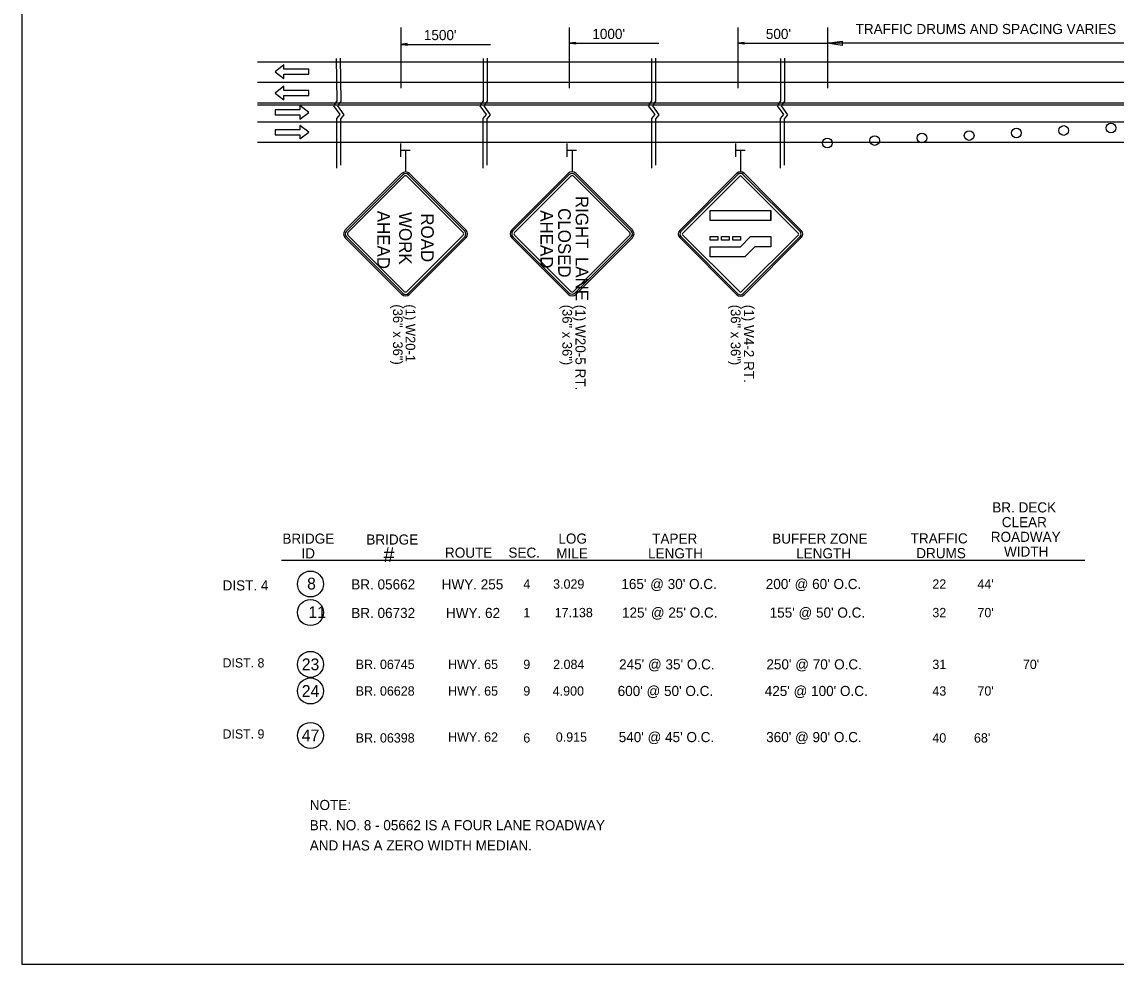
# Model space of a CAD drawing. Extents: x 1930579 to 1938013, y 596452 to 597673.
# Drawn here: x 1936313 to 1936962, y 596573 to 597133 of the extents above; entities that cross this region are included whole.
import ezdxf

# ---------------------------------------------------------------- set-up
doc = ezdxf.new("R2010")
doc.units = 0
for name, color, linetype in [('Default', 7, 'Continuous'), ('P_TC_Signs_Permanent', 7, 'Continuous'), ('P_TC_Signs_Temporary', 7, 'Continuous'), ('R_Border', 7, 'Continuous'), ('R_Striping', 7, 'Continuous'), ('S_AREA_CALC', 7, 'Continuous')]:
    doc.layers.add(name, color=color, linetype=linetype)

msp = doc.modelspace()

# ---------------------------------------------------------------- linework, layer by layer
at = {"layer": 'Default'}
for p, q in [((1936537.79, 597129.19), (1936537.79, 597093.28)), ((1936637.79, 597129.19), (1936637.79, 597093.28)), ((1936737.79, 597129.19), (1936737.79, 597093.28)), ((1936791.02, 597129.19), (1936791.02, 597093.28)), ((1936541.62, 597119.78), (1936537.79, 597119.21)), ((1936537.79, 597119.21), (1936591.02, 597119.21)), ((1936541.62, 597118.63), (1936537.79, 597119.21)), ((1936541.62, 597119.68), (1936538.43, 597119.21)), ((1936541.62, 597118.73), (1936538.43, 597119.21)), ((1936541.62, 597119.59), (1936539.09, 597119.21)), ((1936541.62, 597118.83), (1936539.09, 597119.21)), ((1936541.62, 597119.49), (1936539.73, 597119.21)), ((1936541.62, 597118.92), (1936539.73, 597119.21)), ((1936541.62, 597119.39), (1936540.37, 597119.21)), ((1936541.62, 597119.02), (1936540.37, 597119.21)), ((1936541.62, 597119.3), (1936541.01, 597119.21)), ((1936541.62, 597119.12), (1936541.01, 597119.21)), ((1936541.62, 597118.63), (1936541.62, 597119.78)), ((1936641.62, 597120.46), (1936637.79, 597119.89)), ((1936637.79, 597119.89), (1936691.02, 597119.89)), ((1936641.62, 597119.31), (1936637.79, 597119.89)), ((1936641.62, 597120.36), (1936638.43, 597119.89)), ((1936641.62, 597119.41), (1936638.43, 597119.89)), ((1936641.62, 597120.27), (1936639.09, 597119.89)), ((1936641.62, 597119.51), (1936639.09, 597119.89)), ((1936641.62, 597120.17), (1936639.73, 597119.89)), ((1936641.62, 597119.6), (1936639.73, 597119.89)), ((1936641.62, 597120.07), (1936640.37, 597119.89)), ((1936641.62, 597119.7), (1936640.37, 597119.89)), ((1936641.62, 597119.98), (1936641.01, 597119.89)), ((1936641.62, 597119.8), (1936641.01, 597119.89)), ((1936641.62, 597119.31), (1936641.62, 597120.46)), ((1936741.62, 597120.46), (1936737.79, 597119.89)), ((1936737.79, 597119.89), (1936791.02, 597119.89)), ((1936741.62, 597119.31), (1936737.79, 597119.89)), ((1936741.62, 597120.36), (1936738.43, 597119.89)), ((1936741.62, 597119.41), (1936738.43, 597119.89)), ((1936741.62, 597120.27), (1936739.09, 597119.89)), ((1936741.62, 597119.51), (1936739.09, 597119.89)), ((1936741.62, 597120.17), (1936739.73, 597119.89)), ((1936741.62, 597119.6), (1936739.73, 597119.89)), ((1936741.62, 597120.07), (1936740.37, 597119.89)), ((1936741.62, 597119.7), (1936740.37, 597119.89)), ((1936741.62, 597119.98), (1936741.01, 597119.89)), ((1936741.62, 597119.8), (1936741.01, 597119.89)), ((1936741.62, 597119.31), (1936741.62, 597120.46)), ((1936791.02, 597119.89), (1936799.89, 597121.22)), ((1937015.53, 597119.89), (1936791.02, 597119.89)), ((1936799.89, 597118.56), (1936791.02, 597119.89)), ((1936799.89, 597121.22), (1936799.89, 597118.56)), ((1937804.86, 597108.65), (1936452.69, 597108.65)), ((1937804.86, 597096.65), (1936452.69, 597096.65)), ((1937804.86, 597084.42), (1936452.69, 597084.42)), ((1937804.86, 597083.27), (1936452.69, 597083.27)), ((1937804.86, 597073.09), (1936452.69, 597073.09)), ((1937804.86, 597061.09), (1936452.69, 597061.09)), ((1936537.79, 597052.49), (1936537.79, 597060.47)), ((1936636.62, 597052.43), (1936636.62, 597060.41)), ((1936736.62, 597052.43), (1936736.62, 597060.41)), ((1936537.91, 597056.46), (1936543.36, 597056.46)), ((1936636.74, 597056.4), (1936642.18, 597056.4)), ((1936736.74, 597056.4), (1936742.18, 597056.4))]:
    msp.add_line(p, q, dxfattribs=at)
for points in [[(1936499.33, 597110.93), (1936499.72, 597085.69), (1936497.77, 597082.8), (1936501.57, 597077.6), (1936499.57, 597075.2), (1936499.56, 597045.85)], [(1936501.73, 597111.16), (1936502.12, 597085.59), (1936500.17, 597082.7), (1936503.96, 597077.5), (1936501.96, 597075.1), (1936501.96, 597047.54)], [(1936586.69, 597110.93), (1936586.69, 597085.69), (1936584.74, 597082.8), (1936588.54, 597077.6), (1936586.54, 597075.2), (1936586.54, 597045.85)], [(1936589.09, 597111.16), (1936589.09, 597085.59), (1936587.14, 597082.7), (1936590.94, 597077.5), (1936588.94, 597075.1), (1936588.94, 597047.54)], [(1936686.69, 597110.93), (1936686.69, 597085.69), (1936684.74, 597082.8), (1936688.54, 597077.6), (1936686.54, 597075.2), (1936686.54, 597045.85)], [(1936689.09, 597111.16), (1936689.09, 597085.59), (1936687.14, 597082.7), (1936690.94, 597077.5), (1936688.94, 597075.1), (1936688.94, 597047.54)], [(1936763.16, 597110.93), (1936763.16, 597085.69), (1936761.21, 597082.8), (1936765.01, 597077.6), (1936763.01, 597075.2), (1936763, 597045.85)], [(1936765.56, 597111.16), (1936765.56, 597085.59), (1936763.61, 597082.7), (1936767.4, 597077.5), (1936765.41, 597075.1), (1936765.4, 597047.54)]]:
    msp.add_lwpolyline(points, dxfattribs=at)
for centre, radius in [((1936931.34, 597068.14), 2.87), ((1936959.4, 597069.63), 2.87), ((1936819.09, 597062.2), 2.87), ((1936847.15, 597063.68), 2.87), ((1936875.21, 597065.17), 2.87), ((1936903.28, 597066.66), 2.87), ((1936791.02, 597060.71), 2.87), ((1936484.14, 596798.97), 7.71), ((1936484.14, 596782.01), 7.71), ((1936484.14, 596751.28), 7.71), ((1936484.14, 596735.48), 7.71), ((1936484.14, 596709.1), 7.71)]:
    msp.add_circle(centre, radius, dxfattribs=at)
at = {"layer": 'P_TC_Signs_Permanent'}
for p, q in [((1936703.4, 597008.78), (1936737.34, 597042.72)), ((1936757.46, 597014.7), (1936757.46, 597020.7)), ((1936737.34, 596970.6), (1936703.4, 597004.54)), ((1936775.52, 597004.54), (1936741.58, 596970.6))]:
    msp.add_line(p, q, dxfattribs=at)
for points in [[(1936737.97, 597042.08), (1936704.03, 597008.14)], [(1936705.09, 597007.08), (1936739.04, 597041.02)], [(1936739.88, 597041.02), (1936773.82, 597007.08)], [(1936774.89, 597008.14), (1936740.94, 597042.08)], [(1936741.58, 597042.72), (1936758.55, 597025.75), (1936775.52, 597008.78)], [(1936739.04, 596972.29), (1936705.09, 597006.23)], [(1936773.82, 597006.23), (1936739.88, 596972.29)], [(1936704.03, 597005.17), (1936737.97, 596971.23)], [(1936740.94, 596971.23), (1936774.89, 597005.17)]]:
    msp.add_lwpolyline(points, dxfattribs=at)
for points in [[(1936721.46, 597014.7), (1936721.46, 597020.7), (1936757.46, 597020.7), (1936757.46, 597014.7)], [(1936721.46, 597003.06), (1936721.46, 597005.16), (1936725.96, 597005.16), (1936725.96, 597003.06)], [(1936721.46, 596993.16), (1936721.46, 596999.16), (1936739.46, 596999.16), (1936745.46, 597005.16), (1936757.46, 597005.16), (1936757.46, 596999.16), (1936747.94, 596999.16), (1936741.94, 596993.16)], [(1936728.21, 597003.06), (1936728.21, 597005.16), (1936732.71, 597005.16), (1936732.71, 597003.06)], [(1936734.96, 597003.06), (1936734.96, 597005.16), (1936739.46, 597005.16), (1936739.46, 597003.06)]]:
    msp.add_lwpolyline(points, close=True, dxfattribs=at)
for centre, radius, start, end in [((1936739.46, 597040.6), 3, 45, 135), ((1936739.46, 597040.6), 2.1, 45, 135), ((1936739.46, 597040.6), 0.6, 45, 135), ((1936705.52, 597006.66), 3, 135, 225), ((1936705.52, 597006.66), 2.1, 135, 225), ((1936705.52, 597006.66), 0.6, 135, 225), ((1936773.4, 597006.66), 0.6, 315, 45), ((1936773.4, 597006.66), 2.1, 315, 45), ((1936773.4, 597006.66), 3, 315, 45), ((1936739.46, 596972.72), 3, 225, 315), ((1936739.46, 596972.72), 2.1, 225, 315), ((1936739.46, 596972.72), 0.6, 225, 315)]:
    msp.add_arc(centre, radius, start, end, dxfattribs=at)
at = {"layer": 'P_TC_Signs_Temporary'}
for p, q in [((1936504.84, 597009.13), (1936538.25, 597042.54)), ((1936505.5, 597008.46), (1936538.91, 597041.88)), ((1936506.43, 597007.54), (1936539.84, 597040.95)), ((1936541.43, 597040.95), (1936574.84, 597007.54)), ((1936542.36, 597041.88), (1936575.77, 597008.46)), ((1936543.02, 597042.54), (1936576.43, 597009.13)), ((1936603.66, 597009.2), (1936637.07, 597042.61)), ((1936604.33, 597008.54), (1936637.74, 597041.95)), ((1936605.25, 597007.61), (1936638.66, 597041.02)), ((1936640.26, 597041.02), (1936673.67, 597007.61)), ((1936641.18, 597041.95), (1936674.59, 597008.54)), ((1936641.85, 597042.61), (1936675.26, 597009.2)), ((1936539.84, 596972.53), (1936506.43, 597005.95)), ((1936574.84, 597005.95), (1936541.43, 596972.53)), ((1936638.66, 596972.61), (1936605.25, 597006.02)), ((1936673.67, 597006.02), (1936640.26, 596972.61)), ((1936538.25, 596970.94), (1936504.84, 597004.35)), ((1936538.91, 596971.61), (1936505.5, 597005.02)), ((1936575.77, 597005.02), (1936542.36, 596971.61)), ((1936576.43, 597004.35), (1936543.02, 596970.94)), ((1936637.07, 596971.02), (1936603.66, 597004.43)), ((1936637.74, 596971.68), (1936604.33, 597005.09)), ((1936674.59, 597005.09), (1936641.18, 596971.68)), ((1936675.26, 597004.43), (1936641.85, 596971.02))]:
    msp.add_line(p, q, dxfattribs=at)
for centre, radius, start, end in [((1936540.63, 597040.15), 3.38, 45, 135), ((1936540.63, 597040.15), 2.44, 45, 135), ((1936540.63, 597040.15), 1.12, 45, 135), ((1936639.46, 597040.22), 3.38, 45, 135), ((1936639.46, 597040.22), 2.44, 45, 135), ((1936639.46, 597040.22), 1.12, 45, 135), ((1936507.22, 597006.74), 3.38, 135, 225), ((1936507.22, 597006.74), 2.44, 135, 225), ((1936507.22, 597006.74), 1.13, 135, 225), ((1936574.04, 597006.74), 1.13, 315, 45), ((1936574.04, 597006.74), 2.44, 315, 45), ((1936574.04, 597006.74), 3.38, 315, 45), ((1936606.05, 597006.81), 3.38, 135, 225), ((1936606.05, 597006.81), 2.44, 135, 225), ((1936606.05, 597006.81), 1.13, 135, 225), ((1936672.87, 597006.81), 1.13, 315, 45), ((1936672.87, 597006.81), 2.44, 315, 45), ((1936672.87, 597006.81), 3.38, 315, 45), ((1936540.63, 596973.33), 3.38, 225, 315), ((1936540.63, 596973.33), 2.44, 225, 315), ((1936540.63, 596973.33), 1.12, 225, 315), ((1936639.46, 596973.4), 3.38, 225, 315), ((1936639.46, 596973.4), 2.44, 225, 315), ((1936639.46, 596973.4), 1.12, 225, 315)]:
    msp.add_arc(centre, radius, start, end, dxfattribs=at)
at = {"layer": 'R_Border'}
for p, q in [((1936540.63, 597056.46), (1936540.63, 597043.53)), ((1936639.46, 597056.4), (1936639.46, 597043.6)), ((1936739.46, 597056.4), (1936739.46, 597043.6)), ((1936467.01, 596813.05), (1936943.84, 596813.05))]:
    msp.add_line(p, q, dxfattribs=at)
at = {"layer": 'R_Striping'}
for points in [[(1936468.42, 597107.02), (1936463.23, 597103.02), (1936468.42, 597099.02), (1936468.42, 597101.52), (1936483.13, 597101.52), (1936483.13, 597104.52), (1936468.42, 597104.52)], [(1936468.42, 597094.38), (1936463.23, 597090.38), (1936468.42, 597086.38), (1936468.42, 597088.88), (1936483.13, 597088.88), (1936483.13, 597091.88), (1936468.42, 597091.88)], [(1936477.94, 597074.88), (1936483.13, 597078.88), (1936477.94, 597082.88), (1936477.94, 597080.38), (1936463.23, 597080.38), (1936463.23, 597077.38), (1936477.94, 597077.38)], [(1936477.94, 597063.1), (1936483.13, 597067.1), (1936477.94, 597071.1), (1936477.94, 597068.6), (1936463.23, 597068.6), (1936463.23, 597065.6), (1936477.94, 597065.6)]]:
    msp.add_lwpolyline(points, close=True, dxfattribs=at)
at = {"layer": 'S_AREA_CALC'}
msp.add_lwpolyline([(1938012.84, 597673.36), (1936312.84, 597673.36), (1936312.84, 596573.37), (1938012.84, 596573.37)], close=True, dxfattribs=at)

# ---------------------------------------------------------------- texts
at = {"layer": 'Default'}
for s, p in [('TRAFFIC DRUMS AND SPACING VARIES', (1936807.8, 597125.38)), ("1500'", (1936551.51, 597121.78)), ("1000'", (1936651.51, 597122.45)), ("500'", (1936754.51, 597122.45))]:
    msp.add_text(s, height=6, rotation=360, dxfattribs=at).set_placement(p)
at = {"layer": 'P_TC_Signs_Temporary'}
for s, p in [('RIGHT\u2002LANE', (1936641.59, 597029.33)), (' AHEAD ', (1936523.8, 597023.28)), ('WORK', (1936536.82, 597019.73)), (' AHEAD ', (1936620.71, 597023.59)), ('CLOSED', (1936631.21, 597022.07)), (' ROAD ', (1936549.85, 597021.76))]:
    msp.add_text(s, height=7.5, rotation=270, dxfattribs=at).set_placement(p)
at = {"layer": 'R_Border'}
for s, height, rotation, p in [('(36" x 36")', 5.76, 270, (1936533.14, 596964.96)), ('(1) W20-1', 5.76, 270, (1936540.63, 596964.96)), ('(36" x 36")', 5.76, 270, (1936633.7, 596964.72)), ('(1) W20-5 RT.', 6, 270, (1936641.47, 596964.72)), ('(36" x 36")', 5.76, 270, (1936733.7, 596964.72)), ('(1) W4-2 RT.', 6, 270, (1936741.47, 596964.72)), ('BR. DECK ', 6, 360, (1936888.94, 596841.44)), ('CLEAR', 6, 360, (1936894.58, 596832.7)), ('ROADWAY ', 6, 360, (1936888.04, 596823.97)), ('BRIDGE ', 6, 360, (1936467.51, 596822.9)), ('BRIDGE ', 6, 360, (1936517.35, 596822.38)), ('LOG', 6, 360, (1936631.36, 596822.94)), ('TAPER', 6, 360, (1936687.03, 596822.94)), ('BUFFER ZONE', 6, 360, (1936758.29, 596822.94)), ('TRAFFIC ', 6, 360, (1936840.48, 596823.05)), ('ID', 6, 360, (1936478.82, 596814.17)), ('#', 8.77, 360, (1936527.49, 596811.95)), ('ROUTE', 6, 360, (1936564.04, 596814.58)), ('SEC.', 6, 360, (1936601.68, 596814.58)), ('MILE', 6, 360, (1936630.1, 596814.2)), ('LENGTH', 6, 360, (1936684.59, 596814.2)), ('LENGTH', 6, 360, (1936772.51, 596814.2)), ('DRUMS', 6, 360, (1936843.81, 596814.31)), ('WIDTH', 6, 360, (1936895.93, 596815.23)), ('DIST. 4', 6, 360, (1936432, 596795.14)), ('8', 7, 360, (1936482.16, 596795.71)), ('BR. 05662', 6, 360, (1936508.39, 596795.74)), ('HWY. 255', 6, 360, (1936562.08, 596795.74)), ('4', 5.54, 360, (1936610.52, 596796.2)), ('3.029', 5.54, 360, (1936628.22, 596796.2)), ("165' @ 30' O.C.", 6, 360, (1936668.72, 596795.97)), ("200' @ 60' O.C.", 6, 360, (1936754.46, 596795.97)), ("22         44'", 5.5398, 360, (1936853.36, 596796.2)), ('11', 7, 360, (1936482.98, 596778.76)), ('BR. 06732', 6, 360, (1936508.39, 596778.78)), ('HWY. 62', 6, 360, (1936564.64, 596778.78)), ('1', 5.54, 360, (1936610.52, 596779.24)), ('17.138', 5.54, 360, (1936629.12, 596779.24)), ("125' @ 25' O.C.", 6, 360, (1936669.1, 596779.01)), ("155' @ 50' O.C.", 6, 360, (1936756.77, 596779.01)), ("32         70'", 5.5398, 360, (1936853.36, 596779.24)), ('DIST. 8', 5.475, 360, (1936432, 596749.42)), ('23', 7, 360, (1936479.01, 596747.78)), ('BR. 06745', 5.54, 360, (1936511, 596748.51)), ('HWY. 65', 5.54, 360, (1936565.88, 596748.51)), ('9', 5.54, 360, (1936610.52, 596748.51)), ('2.084', 5.54, 360, (1936628.24, 596748.51)), ("245' @ 35' O.C.", 6, 360, (1936667.4, 596748.28)), ("250' @ 70' O.C.", 6, 360, (1936754.84, 596748.28)), ('31  ', 5.54, 360, (1936853.36, 596748.51)), ("70'", 5.54, 360, (1936907.1, 596748.51)), ('24', 7, 360, (1936479.01, 596731.98)), ('BR. 06628', 5.54, 360, (1936511, 596732.71)), ('HWY. 65', 5.54, 360, (1936565.88, 596732.71)), ('9', 5.54, 360, (1936610.52, 596732.71)), ('4.900', 5.54, 360, (1936628, 596732.71)), ("600' @ 50' O.C.", 6, 360, (1936666.54, 596732.48)), ("425' @ 100' O.C.", 6, 360, (1936753.85, 596732.48)), ("43         70'", 5.5398, 360, (1936853.36, 596732.71)), ('DIST. 9', 5.475, 360, (1936432, 596707.24)), ('47', 7, 360, (1936479.01, 596705.6)), ('BR. 06398', 5.54, 360, (1936511, 596704.87)), ('HWY. 62', 5.54, 360, (1936565.88, 596705.35)), ('6', 5.54, 360, (1936610.52, 596704.87)), ('0.915', 5.54, 360, (1936629.81, 596705.35)), ("540' @ 45' O.C.", 6, 360, (1936667.16, 596705.12)), ("360' @ 90' O.C.", 6, 360, (1936754.7, 596705.12)), ("40        68'", 5.5398, 360, (1936853.36, 596704.87)), ('NOTE:', 6, 360, (1936483.73, 596664.81)), ('BR. NO. 8 - 05662 IS A FOUR LANE ROADWAY', 6, 360, (1936483.73, 596652.81)), ('AND HAS A ZERO WIDTH MEDIAN.', 6, 360, (1936483.73, 596640.81))]:
    msp.add_text(s, height=height, rotation=rotation, dxfattribs=at).set_placement(p)

doc.saveas('drawing.dxf')
